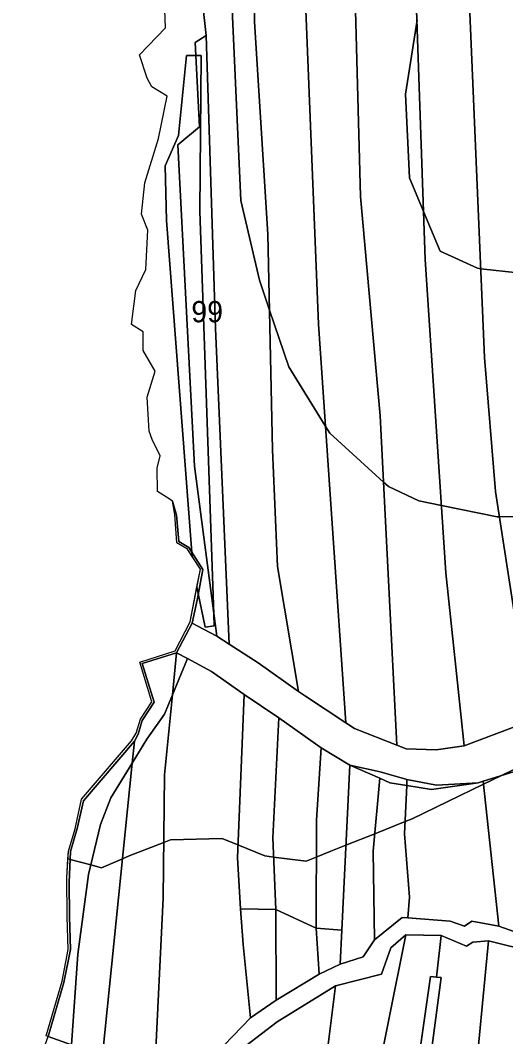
# Model space of a CAD drawing. Extents: x -502026 to -497664, y -1143484 to -1138019.
# Drawn here: x -500030.5 to -499847.9, y -1140705 to -1140322.7 of the extents above; entities that cross this region are included whole.
import ezdxf

# ---------------------------------------------------------------- set-up
doc = ezdxf.new("R2010")
doc.units = 0
for name, color, linetype in [('43', 7, 'Continuous'), ('49', 7, 'Continuous'), ('55', 7, 'Continuous'), ('62', 7, 'Continuous'), ('7', 7, 'Continuous')]:
    doc.layers.add(name, color=color, linetype=linetype)

msp = doc.modelspace()

# ---------------------------------------------------------------- linework, layer by layer
at = {"layer": '43'}
msp.add_lwpolyline([(-499963.34, -1140303.34), (-499960.51, -1140328.44), (-499964.71, -1140331.08), (-499963.09, -1140362.74), (-499971.19, -1140369.6), (-499964.91, -1140490.42), (-499956.6, -1140554.32), (-499964, -1140550.51), (-499965.8, -1140549.45), (-499963.87, -1140540.14), (-499961.81, -1140529.31), (-499967.15, -1140521.01), (-499970.9, -1140518.7), (-499971.7, -1140508.89), (-499973.19, -1140503.53), (-499974.55, -1140502.66), (-499978.88, -1140499.9), (-499979.06, -1140491.17), (-499977.86, -1140486.56), (-499980.85, -1140480.43), (-499982.05, -1140477.3), (-499982.82, -1140464.44), (-499979.77, -1140454.69), (-499984.34, -1140446.91), (-499984.34, -1140439.88), (-499988.68, -1140437.08), (-499987.02, -1140424.4), (-499983.31, -1140416.47), (-499982.55, -1140401.67), (-499984.87, -1140395.59), (-499983.62, -1140383.89), (-499978.52, -1140367.12), (-499975.3, -1140351.27), (-499981.03, -1140347.72), (-499982.73, -1140344.48), (-499985.64, -1140335.76), (-499975.92, -1140325.57), (-499976.24, -1140315.45)], dxfattribs=at)
msp.add_lwpolyline([(-499951.89, -1140557.37), (-499956.6, -1140554.32), (-499964.91, -1140490.42), (-499971.19, -1140369.6), (-499963.09, -1140362.74), (-499964.71, -1140331.08), (-499960.51, -1140328.44), (-499957.09, -1140438.58)], close=True, dxfattribs=at)
at = {"layer": '49'}
msp.add_lwpolyline([(-499965.8, -1140549.45), (-499971.69, -1140560.6), (-499984.68, -1140564.68), (-499980.18, -1140579.14), (-499984.68, -1140586.08), (-499986.21, -1140591.19), (-499987.6, -1140593.79), (-500006.75, -1140616.34), (-500009.08, -1140626.74), (-500011.62, -1140635.39), (-500012.09, -1140646.94), (-500012.06, -1140659.77), (-500011.65, -1140672.26), (-500014.08, -1140684.59), (-500020.01, -1140704.98), (-500020.81, -1140704.65), (-500014.72, -1140684.12), (-500012.53, -1140672.22), (-500012.84, -1140659.78), (-500013.02, -1140645.24), (-500012.39, -1140635.25), (-500009.93, -1140626.85), (-500007.43, -1140615.65), (-499988.72, -1140593.71), (-499986.92, -1140590.79), (-499985.32, -1140585.58), (-499981.02, -1140579), (-499985.55, -1140564.09), (-499972.27, -1140559.93), (-499966.61, -1140548.98), (-499962.72, -1140529.1), (-499967.61, -1140521.66), (-499971.63, -1140519.31), (-499972.3, -1140508.61), (-499973.19, -1140503.53), (-499971.7, -1140508.89), (-499970.9, -1140518.7), (-499967.15, -1140521.01), (-499961.81, -1140529.31), (-499963.87, -1140540.14)], close=True, dxfattribs=at)
for points in [[(-499960.42, -1140715.05), (-499943.9, -1140697.94), (-499934.22, -1140691.29), (-499918.09, -1140681.54), (-499910.16, -1140677.67), (-499901.45, -1140675.02), (-499897.25, -1140668.51), (-499886.87, -1140660.18), (-499884.66, -1140660.35), (-499868.8, -1140661.6), (-499863.38, -1140663.47), (-499860.61, -1140661.6), (-499850.41, -1140663.41), (-499834.87, -1140668.89)], [(-499837.66, -1140673.06), (-499854.33, -1140668.95), (-499860.19, -1140669.4), (-499862.57, -1140670.96), (-499872.09, -1140666.93), (-499885.45, -1140666.7), (-499891.06, -1140671.6), (-499894.54, -1140681.48), (-499911.9, -1140685.93), (-499933.84, -1140699.42), (-499945.58, -1140708.46)], [(-500022.35, -1140711.62), (-500020.01, -1140704.98), (-500011.3, -1140708.04)]]:
    msp.add_lwpolyline(points, dxfattribs=at)
at = {"layer": '55'}
for points in [[(-499841.6, -1140604.33), (-499856.33, -1140608.95), (-499858.2, -1140609.54), (-499873.83, -1140610.41), (-499885.03, -1140608.3), (-499895.05, -1140605.38), (-499906.48, -1140602.92), (-499917.33, -1140596.41), (-499933.2, -1140585.07), (-499946.28, -1140576.33), (-499958.55, -1140567.66), (-499967.6, -1140562.8), (-499971.69, -1140560.6), (-499965.8, -1140549.45), (-499964, -1140550.51), (-499956.6, -1140554.32), (-499951.89, -1140557.37), (-499941.05, -1140564.37), (-499925.79, -1140575.11), (-499923.15, -1140576.97), (-499908.07, -1140586.89), (-499904.7, -1140589.11), (-499888.82, -1140595.39), (-499885.33, -1140596.77), (-499874.03, -1140597.15), (-499863.52, -1140595.59), (-499839.84, -1140586.76)], [(-499883.04, -1140730.6), (-499876.21, -1140682.41), (-499873.89, -1140682.62), (-499872.18, -1140682.78), (-499878.36, -1140730.13)]]:
    msp.add_lwpolyline(points, dxfattribs=at)
for points in [[(-499973.28, -1140576.46), (-499976.28, -1140583.69), (-499982.93, -1140593.05), (-499988.43, -1140602.06), (-499987.6, -1140593.79), (-499986.21, -1140591.19), (-499984.68, -1140586.08), (-499980.18, -1140579.14), (-499984.68, -1140564.68), (-499971.69, -1140560.6)], [(-499967.6, -1140562.8), (-499973.28, -1140576.46), (-499971.69, -1140560.6)], [(-499988.43, -1140602.06), (-499996.44, -1140615.18), (-500000.28, -1140625.14), (-500004.9, -1140644), (-500008.85, -1140673.94), (-500011.3, -1140708.04), (-500020.01, -1140704.98), (-500014.08, -1140684.59), (-500011.65, -1140672.26), (-500012.06, -1140659.77), (-500012.09, -1140646.94), (-500011.62, -1140635.39), (-500009.08, -1140626.74), (-500006.75, -1140616.34), (-499987.6, -1140593.79)], [(-499885.03, -1140608.3), (-499885.04, -1140610.54), (-499891.39, -1140609.52), (-499895.27, -1140607.82), (-499906.48, -1140602.92), (-499895.05, -1140605.38)], [(-499858.2, -1140609.54), (-499875.83, -1140612.02), (-499885.04, -1140610.54), (-499885.03, -1140608.3), (-499873.83, -1140610.41)]]:
    msp.add_lwpolyline(points, close=True, dxfattribs=at)
at = {"layer": '62'}
for points in [[(-499954, -1140246.5), (-499947.5, -1140390.5), (-499940.5, -1140420.5), (-499936.71, -1140431.7), (-499929.5, -1140453), (-499915.73, -1140475.2), (-499914, -1140478), (-499893.78, -1140496.38), (-499892, -1140498), (-499880.5, -1140503.5), (-499872.07, -1140505.21), (-499851, -1140509.5), (-499850.22, -1140509.48), (-499829, -1140509)], [(-499829, -1140509), (-499850.22, -1140509.48), (-499851, -1140509.5), (-499872.07, -1140505.21), (-499880.5, -1140503.5), (-499892, -1140498), (-499893.78, -1140496.38), (-499914, -1140478), (-499915.73, -1140475.2), (-499929.5, -1140453), (-499936.71, -1140431.7), (-499940.5, -1140420.5), (-499947.5, -1140390.5), (-499954, -1140246.5)], [(-499735.62, -1140294.77), (-499755.15, -1140336.03), (-499762, -1140350.5), (-499775.89, -1140370.24), (-499786.96, -1140385.99), (-499794, -1140396), (-499797.84, -1140398.73), (-499816.5, -1140412), (-499818.7, -1140412.72), (-499836.5, -1140418.5), (-499838.7, -1140418.25), (-499857.26, -1140416.14), (-499858.5, -1140416), (-499872.5, -1140409.5), (-499878.74, -1140394.59), (-499884, -1140382), (-499885.5, -1140350.5), (-499881.22, -1140322.63)], [(-499881.22, -1140322.63), (-499885.5, -1140350.5), (-499884, -1140382), (-499878.74, -1140394.59), (-499872.5, -1140409.5), (-499858.5, -1140416), (-499857.26, -1140416.14), (-499838.7, -1140418.25), (-499836.5, -1140418.5), (-499818.7, -1140412.72), (-499816.5, -1140412), (-499797.84, -1140398.73), (-499794, -1140396), (-499786.96, -1140385.99), (-499775.89, -1140370.24), (-499762, -1140350.5), (-499755.15, -1140336.03), (-499735.62, -1140294.77)], [(-499821.9, -1140593.49), (-499849.43, -1140606.78), (-499856.21, -1140610.06), (-499883, -1140623), (-499885.73, -1140624.09), (-499897.12, -1140628.65), (-499907.96, -1140632.98), (-499913.71, -1140635.28), (-499919.12, -1140637.45), (-499923, -1140639), (-499935.21, -1140637.42), (-499938.5, -1140637), (-499948.63, -1140632.88), (-499954.5, -1140630.5), (-499974, -1140631), (-499976.54, -1140631.98), (-499989.5, -1140637), (-499992.08, -1140638.1), (-500000, -1140641.5), (-500004.02, -1140640.42), (-500011.74, -1140638.34), (-500012.57, -1140638.12), (-500012.39, -1140635.25), (-500009.93, -1140626.85), (-500007.43, -1140615.65), (-499988.72, -1140593.71), (-499986.92, -1140590.79), (-499985.32, -1140585.58), (-499981.02, -1140579), (-499985.55, -1140564.09), (-499972.27, -1140559.93), (-499966.61, -1140548.98), (-499964.04, -1140535.83), (-499963.53, -1140538.35), (-499961, -1140551), (-499957.5, -1140550.5), (-499957.65, -1140546.25), (-499963, -1140394.5), (-499962.5, -1140336), (-499964.46, -1140336), (-499968, -1140336), (-499971, -1140366), (-499976, -1140377.5), (-499975.5, -1140398), (-499965.93, -1140522.91), (-499965.81, -1140524.39), (-499967.61, -1140521.66), (-499971.63, -1140519.31), (-499972.3, -1140508.61), (-499973.19, -1140503.53), (-499974.55, -1140502.66), (-499978.88, -1140499.9), (-499979.06, -1140491.17), (-499977.86, -1140486.56), (-499980.85, -1140480.43), (-499982.05, -1140477.3), (-499982.82, -1140464.44), (-499979.77, -1140454.69), (-499984.34, -1140446.91), (-499984.34, -1140439.88), (-499988.68, -1140437.08), (-499987.02, -1140424.4), (-499983.31, -1140416.47), (-499982.55, -1140401.67), (-499984.87, -1140395.59), (-499983.62, -1140383.89), (-499978.52, -1140367.12), (-499975.3, -1140351.27), (-499981.03, -1140347.72), (-499982.73, -1140344.48), (-499985.64, -1140335.76), (-499975.92, -1140325.57), (-499976.24, -1140315.45)], [(-500022.35, -1140711.62), (-500020.01, -1140704.98), (-500020.81, -1140704.65), (-500014.72, -1140684.12), (-500012.53, -1140672.22), (-500012.84, -1140659.78), (-500013.02, -1140645.24), (-500012.57, -1140638.12), (-500011.74, -1140638.34), (-500004.02, -1140640.42), (-500000, -1140641.5), (-499992.08, -1140638.1), (-499989.5, -1140637), (-499976.54, -1140631.98), (-499974, -1140631), (-499954.5, -1140630.5), (-499948.63, -1140632.88), (-499938.5, -1140637), (-499935.21, -1140637.42), (-499923, -1140639), (-499919.12, -1140637.45), (-499913.71, -1140635.28), (-499907.96, -1140632.98), (-499897.12, -1140628.65), (-499885.73, -1140624.09), (-499883, -1140623), (-499856.21, -1140610.06), (-499849.43, -1140606.78), (-499821.9, -1140593.49)]]:
    msp.add_lwpolyline(points, dxfattribs=at)
msp.add_lwpolyline([(-499964.04, -1140535.83), (-499962.72, -1140529.1), (-499965.81, -1140524.39), (-499965.93, -1140522.91), (-499975.5, -1140398), (-499976, -1140377.5), (-499971, -1140366), (-499968, -1140336), (-499964.46, -1140336), (-499962.5, -1140336), (-499963, -1140394.5), (-499957.65, -1140546.25), (-499957.5, -1140550.5), (-499961, -1140551), (-499963.53, -1140538.35)], close=True, dxfattribs=at)
at = {"layer": '7'}
for points in [[(-499816.74, -1140573.4), (-499838.34, -1140585.89), (-499851.71, -1140499.91), (-499855.86, -1140449.52), (-499863.55, -1140266.72), (-499864.57, -1140154.99), (-499880.85, -1140048.12), (-499891.36, -1139996.58), (-499904.88, -1139943.27), (-499884.38, -1139938.41), (-499862.01, -1140041.94), (-499844.53, -1140157.68), (-499844.58, -1140207.46), (-499841.78, -1140313.52), (-499838.69, -1140418.67), (-499830.44, -1140498.11)], [(-499838.34, -1140585.89), (-499839.84, -1140586.76), (-499863.52, -1140595.59), (-499870.42, -1140530.55), (-499878.11, -1140412.7), (-499881.61, -1140311.46), (-499885.03, -1140210.22), (-499882.47, -1140154.07), (-499897.33, -1140059.68), (-499922.32, -1139947.41), (-499904.88, -1139943.27), (-499891.36, -1139996.58), (-499880.85, -1140048.12), (-499864.57, -1140154.99), (-499863.55, -1140266.72), (-499855.86, -1140449.52), (-499851.71, -1140499.91)], [(-499863.52, -1140595.59), (-499874.03, -1140597.15), (-499885.33, -1140596.77), (-499888.82, -1140595.39), (-499895.03, -1140471.44), (-499902.51, -1140388.93), (-499904.81, -1140304.86), (-499905.02, -1140257.89), (-499908.28, -1140150.5), (-499919.3, -1140065.49), (-499934.93, -1139994.82), (-499944.43, -1139957.91), (-499922.32, -1139947.41), (-499897.33, -1140059.68), (-499882.47, -1140154.07), (-499885.03, -1140210.22), (-499881.61, -1140311.46), (-499878.11, -1140412.7), (-499870.42, -1140530.55)], [(-499888.82, -1140595.39), (-499904.7, -1140589.11), (-499908.07, -1140586.89), (-499918.35, -1140437.06), (-499924.5, -1140284.56), (-499926.81, -1140148.91), (-499936.81, -1140075.83), (-499961.73, -1139966.13), (-499944.43, -1139957.91), (-499934.93, -1139994.82), (-499919.3, -1140065.49), (-499908.28, -1140150.5), (-499905.02, -1140257.89), (-499904.81, -1140304.86), (-499902.51, -1140388.93), (-499895.03, -1140471.44)], [(-499908.07, -1140586.89), (-499923.15, -1140576.97), (-499925.79, -1140575.11), (-499933.77, -1140528.1), (-499935.59, -1140484.22), (-499937.32, -1140403.13), (-499942.44, -1140323.33), (-499942.44, -1140254.07), (-499945.57, -1140152.32), (-499945.51, -1140144.62), (-499951.85, -1140089.69), (-499953.58, -1140082.22), (-499977.96, -1139977.93), (-499978.72, -1139974.68), (-499961.73, -1139966.13), (-499936.81, -1140075.83), (-499926.81, -1140148.91), (-499924.5, -1140284.56), (-499918.35, -1140437.06)], [(-499925.79, -1140575.11), (-499941.05, -1140564.37), (-499951.89, -1140557.37), (-499957.09, -1140438.58), (-499960.51, -1140328.44), (-499963.34, -1140303.34), (-499962.64, -1140297.82), (-499966.45, -1140280.67), (-499965.74, -1140158.57), (-499945.57, -1140152.32), (-499942.44, -1140254.07), (-499942.44, -1140323.33), (-499937.32, -1140403.13), (-499935.59, -1140484.22), (-499933.77, -1140528.1)], [(-499946.28, -1140576.33), (-499948.83, -1140637.74), (-499947.62, -1140656.86), (-499946.68, -1140670.34), (-499943.9, -1140697.94), (-499960.42, -1140715.05), (-499979.83, -1140717.33), (-499976.75, -1140652.92), (-499976.28, -1140606.52), (-499973.28, -1140576.46), (-499967.6, -1140562.8), (-499958.55, -1140567.66)], [(-499979.83, -1140717.33), (-499983.14, -1140717.72), (-499999.56, -1140712.07), (-499988.43, -1140602.06), (-499982.93, -1140593.05), (-499976.28, -1140583.69), (-499973.28, -1140576.46), (-499976.28, -1140606.52), (-499976.75, -1140652.92)], [(-499933.2, -1140585.07), (-499935.51, -1140630.16), (-499934.39, -1140657.18), (-499947.62, -1140656.86), (-499948.83, -1140637.74), (-499946.28, -1140576.33)], [(-499917.33, -1140596.41), (-499919.1, -1140623.51), (-499919.15, -1140664.2), (-499934.39, -1140657.18), (-499935.51, -1140630.16), (-499933.2, -1140585.07)], [(-499906.48, -1140602.92), (-499909.53, -1140664.92), (-499919.15, -1140664.2), (-499919.1, -1140623.51), (-499917.33, -1140596.41)], [(-499999.56, -1140712.07), (-500011.3, -1140708.04), (-500008.85, -1140673.94), (-500004.9, -1140644), (-500000.28, -1140625.14), (-499996.44, -1140615.18), (-499988.43, -1140602.06)], [(-499895.27, -1140607.82), (-499897.7, -1140635.22), (-499897.25, -1140668.51), (-499901.45, -1140675.02), (-499910.16, -1140677.67), (-499909.53, -1140664.92), (-499906.48, -1140602.92)], [(-499830.69, -1140669.85), (-499834.87, -1140668.89), (-499850.41, -1140663.41), (-499856.33, -1140608.95), (-499841.6, -1140604.33)], [(-499885.04, -1140610.54), (-499885.96, -1140628.67), (-499884.09, -1140652.58), (-499884.66, -1140660.35), (-499886.87, -1140660.18), (-499897.25, -1140668.51), (-499897.7, -1140635.22), (-499895.27, -1140607.82), (-499891.39, -1140609.52)], [(-499850.41, -1140663.41), (-499860.61, -1140661.6), (-499863.38, -1140663.47), (-499868.8, -1140661.6), (-499884.66, -1140660.35), (-499884.09, -1140652.58), (-499885.96, -1140628.67), (-499885.04, -1140610.54), (-499875.83, -1140612.02), (-499858.2, -1140609.54), (-499856.33, -1140608.95)], [(-499934.39, -1140657.18), (-499934.22, -1140691.29), (-499943.9, -1140697.94), (-499946.68, -1140670.34), (-499947.62, -1140656.86)], [(-499919.15, -1140664.2), (-499918.09, -1140681.54), (-499934.22, -1140691.29), (-499934.39, -1140657.18)], [(-499909.53, -1140664.92), (-499910.16, -1140677.67), (-499918.09, -1140681.54), (-499919.15, -1140664.2)], [(-499898.57, -1140732.21), (-499919.69, -1140734.41), (-499915.25, -1140712.9), (-499911.9, -1140685.93), (-499894.54, -1140681.48), (-499891.06, -1140671.6), (-499885.45, -1140666.7)], [(-499872.09, -1140666.93), (-499873.89, -1140682.62), (-499876.21, -1140682.41), (-499883.04, -1140730.6), (-499898.57, -1140732.21), (-499885.45, -1140666.7)], [(-499854.33, -1140668.95), (-499860, -1140727.83), (-499878.36, -1140730.13), (-499872.18, -1140682.78), (-499873.89, -1140682.62), (-499872.09, -1140666.93), (-499862.57, -1140670.96), (-499860.19, -1140669.4)], [(-499837.66, -1140673.06), (-499839.09, -1140721.5), (-499839.25, -1140725.22), (-499860, -1140727.83), (-499854.33, -1140668.95)], [(-499919.69, -1140734.41), (-499951.28, -1140737.77), (-500003.84, -1140735.4), (-500004.95, -1140738.09), (-500030.51, -1140734.81), (-500022.35, -1140711.62), (-499998.2, -1140719.75), (-499980.36, -1140723.74), (-499957.39, -1140721.24), (-499945.58, -1140708.46), (-499933.84, -1140699.42), (-499911.9, -1140685.93), (-499915.25, -1140712.9)]]:
    msp.add_lwpolyline(points, close=True, dxfattribs=at)

# ---------------------------------------------------------------- texts
at = {"layer": '62'}
msp.add_text('99', height=8, dxfattribs=at).set_placement((-499966.14, -1140436.3))

doc.saveas('drawing.dxf')
